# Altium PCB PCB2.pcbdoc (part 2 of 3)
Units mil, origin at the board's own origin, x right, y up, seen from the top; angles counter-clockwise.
Board outline 1771.65 x 2755.61 mil, 4 copper layers (Top Layer, Inner1, Inner2, Bottom Layer), stack 62.447 mil thick; 80 components, 88 nets, 409 pads, 183 vias.
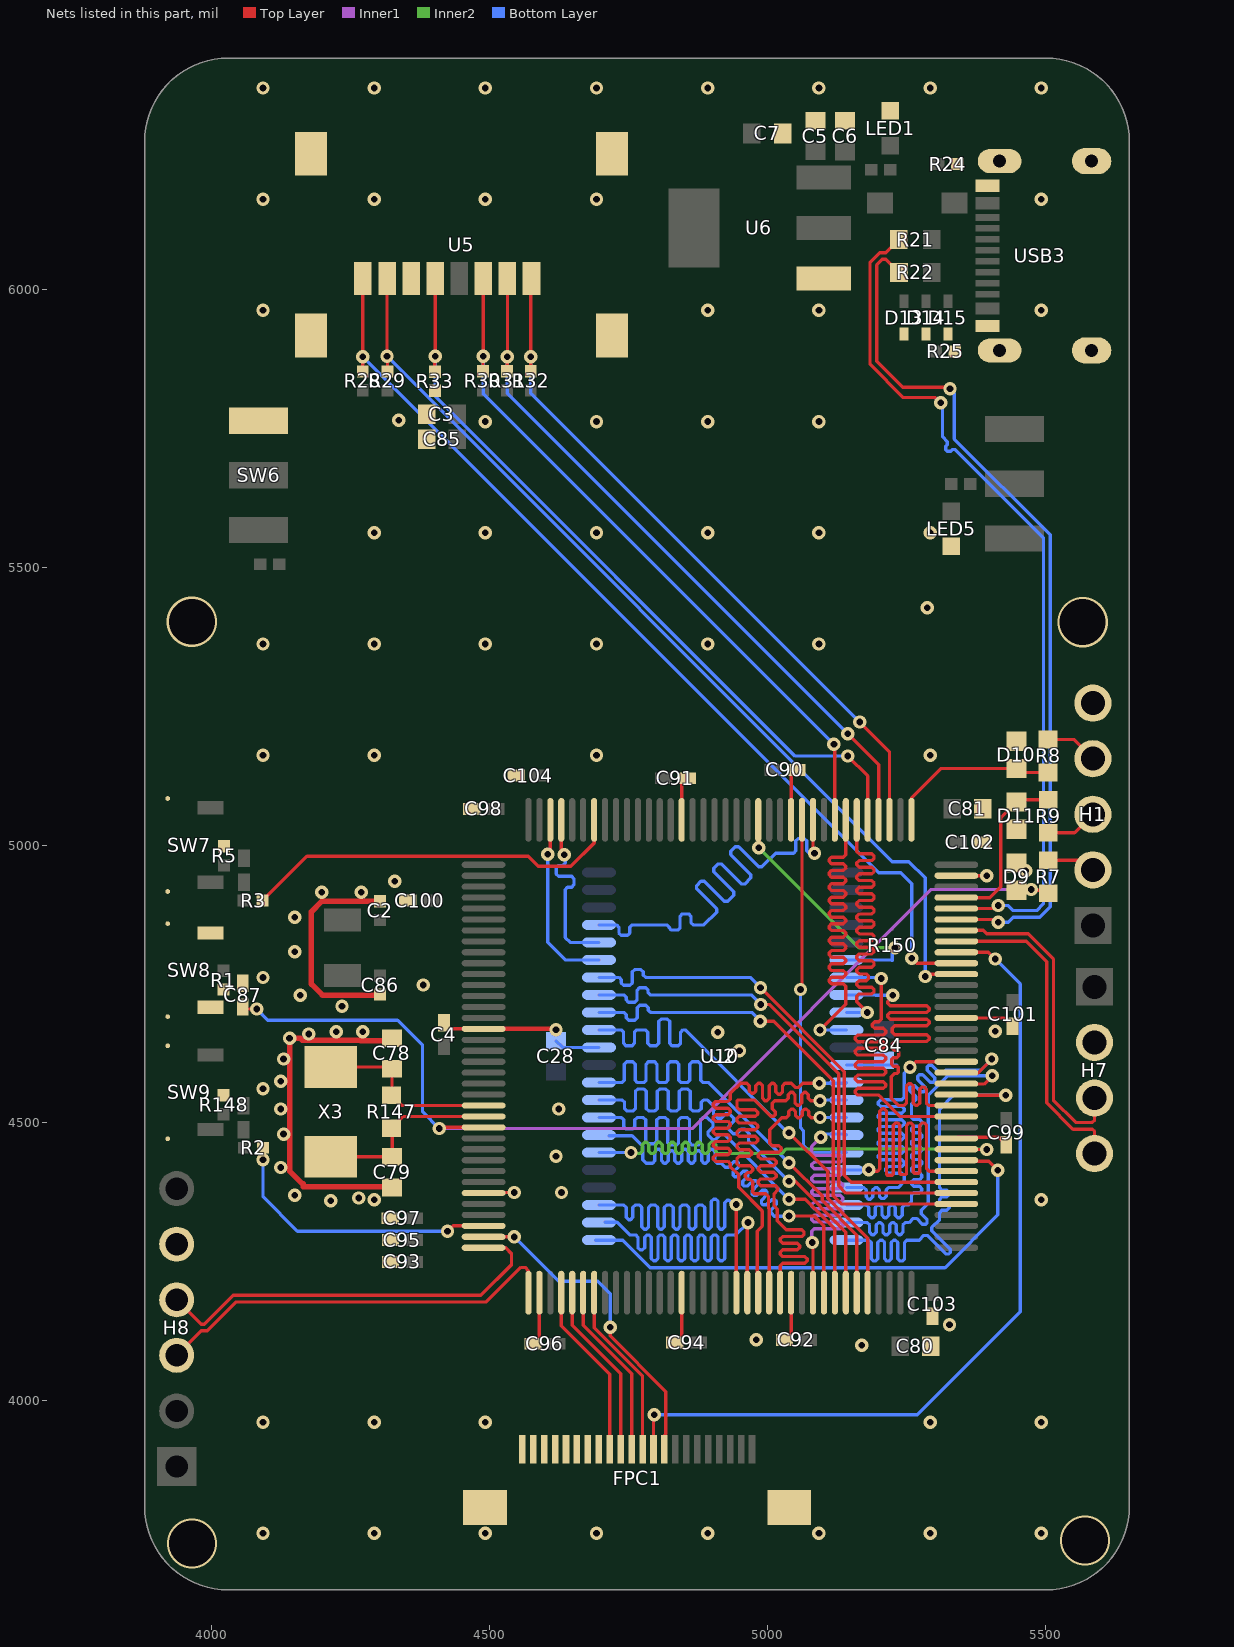
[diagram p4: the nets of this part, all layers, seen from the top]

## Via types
v1: diameter 24.02, hole 12.01, Top Layer to Bottom Layer, 179 vias
v2: diameter 90.55, hole 82.68, Top Layer to Bottom Layer, 4 vias

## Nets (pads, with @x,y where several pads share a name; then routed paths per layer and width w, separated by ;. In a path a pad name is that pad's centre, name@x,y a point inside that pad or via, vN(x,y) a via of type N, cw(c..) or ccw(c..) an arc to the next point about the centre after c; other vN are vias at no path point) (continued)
A10: U2.25 U10.56 | length 947.2
  Top Layer w6: U10.56@4944.53,4194.8 v1(4944.53,4353.18)
  Bottom Layer w6: U2.25@4697.34,4352.28 4742.07,4352.28 4746.31,4348.04 4746.31,4330.07 4750.55,4325.82 4754.07,4325.82 4758.31,4330.07 4758.31,4348.04 4762.55,4352.28 4770.31,4352.28 4774.55,4348.04 4774.55,4312.85 4778.8,4308.6 4782.31,4308.6 4786.55,4312.85 4786.55,4348.04 4790.8,4352.28 4798.55,4352.28 4802.8,4348.04 4802.8,4312.85 4807.04,4308.6 4810.55,4308.6 4814.8,4312.85 4814.8,4348.04 4819.04,4352.28 4826.8,4352.28 4831.04,4348.04 4831.04,4312.85 4835.28,4308.6 4838.8,4308.6 4843.04,4312.85 4843.04,4348.04 4847.28,4352.28 4855.04,4352.28 4859.28,4348.04 4859.28,4312.85 4863.53,4308.6 4867.04,4308.6 4871.28,4312.85 4871.28,4348.04 4875.53,4352.28 4883.28,4352.28 4887.53,4348.04 4887.53,4312.85 4891.77,4308.6 4895.28,4308.6 4899.53,4312.85 4899.53,4358.81 4903.77,4363.05 4907.28,4363.05 4911.53,4358.81 4911.53,4312.85 4915.77,4308.6 4919.28,4308.6 4923.53,4312.85 4923.53,4356.64 4927.77,4360.88 4931.28,4360.88 4935.53,4356.64 4935.53,4356.52 4939.77,4352.28 4943.63,4352.28 v1(4944.53,4353.18)
A11: U2.24 U10.57 | length 947.5
  Top Layer w6: U10.57@4964.21,4194.8 4964.21,4319.48 v1(4965.52,4320.79)
  Bottom Layer w6: U2.24@4708.95,4321.6 4729.9,4321.6 4752.91,4298.59 4763.29,4298.59 4767.53,4294.34 4767.53,4275.77 4771.78,4271.53 4775.29,4271.53 4779.53,4275.77 4779.53,4294.34 4783.78,4298.59 4787.29,4298.59 4791.53,4294.34 4791.53,4256.08 4795.78,4251.84 4799.29,4251.84 4803.53,4256.08 4803.53,4294.34 4807.78,4298.59 4811.29,4298.59 4815.53,4294.34 4815.53,4256.08 4819.78,4251.84 4823.29,4251.84 4827.53,4256.08 4827.53,4294.34 4831.78,4298.59 4835.29,4298.59 4839.53,4294.34 4839.53,4256.08 4843.78,4251.84 4847.29,4251.84 4851.53,4256.08 4851.53,4294.34 4855.78,4298.59 4859.29,4298.59 4863.53,4294.34 4863.53,4256.08 4867.78,4251.84 4871.29,4251.84 4875.53,4256.08 4875.53,4294.34 4879.78,4298.59 4883.29,4298.59 4887.53,4294.34 4887.53,4256.08 4891.78,4251.84 4895.29,4251.84 4899.53,4256.08 4899.53,4294.34 4903.78,4298.59 4907.29,4298.59 4911.53,4294.34 4911.53,4256.08 4915.78,4251.84 4919.29,4251.84 4923.53,4256.08 4923.53,4294.34 4927.78,4298.59 4943.59,4298.59 4965.52,4320.52 v1(4965.52,4320.79)
A12: U2.22 U10.87 | length 946.8
  Top Layer w6: U10.87@5340.2,4551.1 5341.3,4550 v1(5429.01,4550)
  Bottom Layer w6: U2.22@5142.66,4289.29 5182.78,4289.29 5187.02,4285.05 5187.02,4255.8 5191.26,4251.55 5194.78,4251.55 5199.02,4255.8 5199.02,4285.05 5203.26,4289.29 5206.78,4289.29 5211.02,4285.05 5211.02,4255.8 5215.26,4251.55 5218.78,4251.55 5223.02,4255.8 5223.02,4285.05 5227.26,4289.29 5230.78,4289.29 5235.02,4285.05 5235.02,4255.8 5239.26,4251.55 5242.78,4251.55 5247.02,4255.8 5247.02,4285.05 5251.26,4289.29 5273.31,4289.29 5281.61,4297.59 5287.61,4297.59 5320.83,4264.37 5326.83,4264.37 5329.31,4266.86 5329.31,4272.86 5296.1,4306.07 5296.1,4312.07 5310,4325.98 5310,4338.73 5314.24,4342.97 5322.98,4342.97 5327.23,4347.21 5327.23,4350.73 5322.98,4354.97 5314.24,4354.97 5310,4359.21 5310,4362.73 5314.24,4366.97 5322.98,4366.97 5327.23,4371.21 5327.23,4374.73 5322.98,4378.97 5314.24,4378.97 5310,4383.21 5310,4525 5335,4550 v1(5429.01,4550)
A13: U2.21 U10.88 | length 696.3
  Top Layer w6: U10.88@5340.2,4570.79 5340.99,4570 5390,4570 v1(5405,4585)
  Bottom Layer w6: U2.21@5142.66,4320.79 5179.91,4320.79 5184.15,4316.55 5184.15,4302.96 5188.4,4298.72 5191.91,4298.72 5196.15,4302.96 5196.15,4316.55 5200.4,4320.79 5203.91,4320.79 5208.15,4316.55 5208.15,4302.96 5212.4,4298.72 5215.91,4298.72 5220.15,4302.96 5220.15,4316.55 5224.4,4320.79 5227.91,4320.79 5232.15,4316.55 5232.15,4302.96 5236.4,4298.72 5239.91,4298.72 5244.15,4302.96 5244.15,4316.55 5248.4,4320.79 5255.15,4320.79 5262.61,4328.25 5268.61,4328.25 5279.12,4317.74 5285.12,4317.74 5287.6,4320.23 5287.6,4326.23 5277.09,4336.74 5277.09,4342.74 5290,4355.64 5290,4550 5325,4585 v1(5405,4585)
A14: U2.20 U10.89 | length 945.9
  Top Layer w6: U10.89@5340.2,4590.47 5379.5,4590.47 v1(5404.03,4615)
  Bottom Layer w6: U2.20@5142.66,4352.28 5178.39,4352.28 5182.64,4348.04 5182.64,4333.81 5186.88,4329.56 5190.39,4329.56 5194.64,4333.81 5194.64,4348.04 5198.88,4352.28 5202.39,4352.28 5206.64,4348.04 5206.64,4333.81 5210.88,4329.56 5214.39,4329.56 5218.64,4333.81 5218.64,4348.04 5222.88,4352.28 5226.39,4352.28 5230.64,4348.04 5230.64,4333.81 5234.88,4329.56 5238.39,4329.56 5242.64,4333.81 5242.64,4348.04 5246.88,4352.28 5253.55,4352.28 5259.55,4358.28 5259.55,4369.98 5263.79,4374.22 5273.98,4374.22 5278.23,4378.47 5278.23,4381.98 5273.98,4386.22 5263.79,4386.22 5259.55,4390.47 5259.55,4393.98 5263.79,4398.22 5273.98,4398.22 5278.23,4402.47 5278.23,4405.98 5273.98,4410.22 5263.79,4410.22 5259.55,4414.47 5259.55,4417.98 5263.79,4422.22 5273.98,4422.22 5278.23,4426.47 5278.23,4429.98 5273.98,4434.22 5263.79,4434.22 5259.55,4438.47 5259.55,4441.98 5263.79,4446.22 5273.98,4446.22 5278.23,4450.47 5278.23,4453.98 5273.98,4458.22 5263.79,4458.22 5259.55,4462.47 5259.55,4465.98 5263.79,4470.22 5273.98,4470.22 5278.23,4474.47 5278.23,4477.98 5273.98,4482.22 5263.79,4482.22 5259.55,4486.47 5259.55,4489.98 5263.79,4494.22 5273.98,4494.22 5278.23,4498.47 5278.23,4501.98 5273.98,4506.22 5263.79,4506.22 5259.55,4510.47 5259.55,4533.71 5267.46,4541.62 5267.46,4547.62 5256.72,4558.37 5256.72,4564.37 5259.2,4566.85 5265.2,4566.85 5275.94,4556.11 5281.94,4556.11 5284.43,4558.59 5284.43,4564.59 5270.91,4578.11 5270.91,4584.11 5273.4,4586.59 5279.4,4586.59 5292.91,4573.08 5298.91,4573.08 5301.4,4575.56 5301.4,4581.56 5287.88,4595.08 5287.88,4601.08 5290.37,4603.57 5296.37,4603.57 5309.89,4590.05 5315.89,4590.05 5320.85,4595.02 5384.05,4595.02 v1(5404.03,4615)
A15: U2.19 U10.90 | length 941
  Top Layer w6: v1(5256.95,4600) 5267.11,4610.16 U10.90@5340.2,4610.16
  Bottom Layer w6: U2.19@5142.66,4383.78 5173.7,4383.78 5177.94,4379.54 5177.94,4366.89 5182.18,4362.65 5185.7,4362.65 5189.94,4366.89 5189.94,4379.54 5194.18,4383.78 5197.7,4383.78 5201.94,4379.54 5201.94,4368.3 5206.18,4364.05 5209.7,4364.05 5213.94,4368.3 5213.94,4379.54 5218.18,4383.78 5235.77,4383.78 5246.7,4394.71 5246.7,4405.42 5242.46,4409.66 5217.63,4409.66 5213.39,4413.9 5213.39,4417.42 5217.63,4421.66 5242.46,4421.66 5246.7,4425.9 5246.7,4429.42 5242.46,4433.66 5204.28,4433.66 5200.04,4437.9 5200.04,4441.42 5204.28,4445.66 5242.46,4445.66 5246.7,4449.9 5246.7,4453.42 5242.46,4457.66 5204.28,4457.66 5200.04,4461.9 5200.04,4465.42 5204.28,4469.66 5242.46,4469.66 5246.7,4473.9 5246.7,4477.42 5242.46,4481.66 5204.28,4481.66 5200.04,4485.9 5200.04,4489.42 5204.28,4493.66 5242.46,4493.66 5246.7,4497.9 5246.7,4501.42 5242.46,4505.66 5204.28,4505.66 5200.04,4509.9 5200.04,4513.42 5204.28,4517.66 5242.46,4517.66 5246.7,4521.9 5246.7,4525.42 5242.46,4529.66 5204.28,4529.66 5200.04,4533.9 5200.04,4537.42 5204.28,4541.66 5242.46,4541.66 5246.7,4545.9 5246.7,4589.75 v1(5256.95,4600)
A16: U2.18 U10.80 | length 946.9
  Top Layer w6: v1(5182.53,4415.91) 5185.13,4413.31 5198.44,4413.31 5202.68,4417.55 5202.68,4521.15 5206.93,4525.4 5210.44,4525.4 5214.68,4521.15 5214.68,4407.32 5216.07,4405.93 5225.29,4405.93 5226.68,4407.32 5226.68,4495.71 5230.93,4499.96 5234.44,4499.96 5238.68,4495.71 5238.68,4408.77 5240.07,4407.39 5249.22,4407.39 5250.68,4408.84 5250.68,4495.71 5254.93,4499.96 5258.44,4499.96 5262.68,4495.71 5262.68,4411.33 5264.48,4409.54 5273.01,4409.54 5274.68,4411.21 5274.68,4495.71 5278.93,4499.96 5282.44,4499.96 5286.68,4495.71 5286.68,4417.55 5290.93,4413.31 U10.80@5340.2,4413.31
  Bottom Layer w6: U2.18@5142.66,4415.28 5181.9,4415.28 v1(5182.53,4415.91)
A17: U2.23 U10.81 | length 945
  Top Layer w6: U10.81@5340.2,4432.99 5341.89,4431.3 5398.7,4431.3 v1(5415,4415)
  Bottom Layer w6: U2.23@4691.26,4289.16 4739.99,4289.16 4789.36,4239.78 5319.87,4239.78 5414.94,4334.86 v1@5414.94,4414.04
A18: U2.28 U10.82 | length 946
  Top Layer w6: U10.82@5338.79,4452.37 5338.87,4452.3 v1(5395.08,4452.3)
  Inner2 w6: v1@4749.03,4445.05 4770.9,4445.05 4775.14,4449.29 4775.14,4460.98 4779.39,4465.22 4782.9,4465.22 4787.14,4460.98 4787.14,4449.29 4791.39,4445.05 4794.9,4445.05 4799.14,4449.29 4799.14,4460.98 4803.39,4465.22 4806.9,4465.22 4811.14,4460.98 4811.14,4449.29 4815.39,4445.05 4818.9,4445.05 4823.14,4449.29 4823.14,4460.98 4827.39,4465.22 4830.9,4465.22 4835.14,4460.98 4835.14,4449.29 4839.39,4445.05 4842.9,4445.05 4847.14,4449.29 4847.14,4460.98 4851.39,4465.22 4854.9,4465.22 4859.14,4460.98 4859.14,4449.29 4863.39,4445.05 4866.9,4445.05 4871.14,4449.29 4871.14,4460.98 4875.39,4465.22 4878.9,4465.22 4883.14,4460.98 4883.14,4449.29 4887.39,4445.05 4890.9,4445.05 4895.14,4449.29 4895.14,4460.98 4899.39,4465.22 4902.9,4465.22 4907.14,4460.98 4907.14,4449.29 4911.39,4445.05 5025.79,4445.05 5033.75,4453.01 5394.37,4453.01 v1(5395.08,4452.3)
  Bottom Layer w6: U2.28@4697.34,4446.77 v1(4755,4446.77)
BOOT0: R3.1 U10.138 | length 696.3
  Top Layer w6: R3.1@4092.04,4900 4172.04,4980 4570,4980 4588.32,4961.68 4646.68,4961.68 4688.62,5003.62 U10.138@4688.62,5045.2
CLK: H1.4 R8.1 | length 94.7
  Top Layer w6: R8.1@5505.48,5189.88 5551.24,5189.88 H1.4@5585.85,5155.26
CS: R150.2 U2.6 U10.123 | length 477.5
  Top Layer w5.98: U10.123@4983.9,5045.2 4985,5044.1 v1(4985,4995)
  Inner2 w5.98: v1(4985,4995) 5165,4815 v1(5230,4815)
  Bottom Layer w5.98: R150.2@5225,4792.44 5225,4810 v1(5230,4815)
  Bottom Layer w6: U2.6@5142.66,4793.23 5224.21,4793.23 R150.2@5225,4792.44
DAISY: FPC1.9 U10.35 | length 592
  Top Layer w6: U10.35@4489.8,4295.2 4490,4295 v1(4545,4295) ; v1(4717.39,4132.3) 4717.39,4116.78 4817.78,4016.38 4817.78,3940.42 4815.09,3937.72 FPC1.9@4815.09,3913.35
  Bottom Layer w6: v1(4545,4295) 4625,4215 4695,4215 4717.39,4192.61 v1(4717.39,4132.3)
DIO: H1.3 R9.1 | length 93.9
  Top Layer w6: R9.1@5505.63,5022.3 5552.9,5022.3 H1.3@5585.85,5055.26
GND: C2.1 C3.1 C4.1 C5.1 C6.1 C7.2 C28.2 C78.1 C79.1 C80.2 C81.2 C84.2 C85.1 C86.1 C87.1 C90.2 C91.2 C92.2 C93.2 C94.2 C95.2 C96.2 C97.2 C98.2 C99.2 C100.2 C101.2 C102.2 C103.2 C104.1 D9.2 D10.2 D11.2 D13.1 D14.1 D15.1 FPC1.15 FPC1.16 FPC1.17 FPC1.18 FPC1.19 FPC1.20 FPC1.21 FPC1.22 FPC1.23 FPC1.24 H1.5 H7.2 H8.5 LED1.1 LED5.1 R5.2 R24.2 R25.2 R33.2 R148.2 SW6.3 SW7.3 SW7.4 SW8.2 SW8.3 SW8.4 SW9.3 SW9.4 U2.12 U2.34 U5.6 U5.9 U5.10 U5.11 U5.12 U6.1 U10.16 U10.31 U10.38 U10.51 U10.61 U10.83 U10.94 U10.107 U10.120 U10.130 USB3.1 USB3.12 USB3.13 USB3.14 | length 2169.7
  Top Layer w6: C4.1@4418.54,4680.5 4429.83,4669.21 U10.16@4489.8,4669.21 ; U10.31@4489.8,4373.94 4490.86,4375 v1(4545,4375) ; C96.2@4578.7,4102.72 4590.2,4114.22 U10.38@4590.2,4194.8 ; C94.2@4833.54,4105 4846.1,4117.56 U10.51@4846.1,4194.8 ; U10.130@4846.1,5045.2 4846.1,5109.64 C91.2@4856.46,5120 ; C92.2@5031.05,4109.69 5042.95,4121.59 U10.61@5042.95,4194.8 ; U10.120@5042.95,5045.2 5042.95,5124.76 C90.2@5053.19,5135 ; U10.83@5340.2,4472.36 5342.2,4474.36 5416.56,4474.36 C99.2@5429.86,4461.05 ; U10.94@5340.2,4688.9 5426.3,4688.9 C101.2@5441.34,4673.86 ; U10.107@5340.2,4944.8 v1(5395.2,4944.8)
  Top Layer w7.87: U10.16@4489.8,4669.21 4618.7,4669.21 v1(4620,4667.91)
  Top Layer w10: C2.1@4303.59,4899.16 4199.16,4899.16 4180,4880 4180,4750 4200,4730 4302.58,4730 C86.1@4303.65,4731.06 ; C78.1@4325,4652.56 4320,4647.56 4268.33,4647.56 4266.79,4649.1 4163.21,4649.1 4159.74,4652.56 v1(4140.79,4652.56) 4140.79,4413.32 4163.21,4390.9 4164.36,4390.9 4165,4390.27 4165,4385 4324.1,4385 C79.1@4325.2,4383.89
  Bottom Layer w6: C28.2@4620,4647.56 4631.81,4635.75 U2.34@4697.34,4635.75 ; U2.12@5142.66,4604.25 5233.19,4604.25
  other v1: 4093.03,3761.73 4293.03,3761.73 4493.03,3761.73 4693.03,3761.73 4893.03,3761.73 5093.03,3761.73 5293.03,3761.73 5493.03,3761.73 4093.03,3961.73 4293.03,3961.73 4493.03,3961.73 5293.03,3961.73 5493.03,3961.73 5170,4100 4980,4110 5328.03,4136.73 4215,4360 4293.03,4361.73 5493.03,4361.73 4265,4365 4150,4370 4630,4375 4125,4420 4620,4440 4130,4480 4125,4525 4625,4525 4093.03,4561.73 4125,4575 4130,4615 4950,4630 4175,4660 4911.06,4663.17 4225,4664.01 4272.56,4664.01 5410,4665 4235,4710 4160,4730 4381.02,4748.1 4093.03,4761.73 4150,4808.18 4150,4870 4198.73,4915 4270,4915 4330,4935 5465,4953.79 4093.03,5161.73 4293.03,5161.73 4693.03,5161.73 5293.03,5161.73 4093.03,5361.73 4293.03,5361.73 4493.03,5361.73 4693.03,5361.73 4893.03,5361.73 5093.03,5361.73 5288.03,5426.73 4293.03,5561.73 4493.03,5561.73 4693.03,5561.73 4893.03,5561.73 5093.03,5561.73 5293.03,5561.73 4493.03,5761.73 4693.03,5761.73 4893.03,5761.73 5093.03,5761.73 4336.89,5764.22 4093.03,5961.73 4893.03,5961.73 5093.03,5961.73 5493.03,5961.73 4093.03,6161.73 4293.03,6161.73 4493.03,6161.73 4693.03,6161.73 5493.03,6161.73 4093.03,6361.73 4293.03,6361.73 4493.03,6361.73 4693.03,6361.73 4893.03,6361.73 5093.03,6361.73 5293.03,6361.73 5493.03,6361.73
  other v2: 3965.18,3743.42 5571.73,3748.98 5567.35,5401.03 3964.91,5401.64
IO0: U2.7 U10.85 | length 947.3
  Top Layer w6: v1(5205,4760) 5205,4686.39 5200.76,4682.15 5193.1,4682.15 5188.86,4677.91 5188.86,4674.39 5193.1,4670.15 5208.98,4670.15 5213.23,4665.91 5213.23,4662.39 5208.98,4658.15 5162.71,4658.15 5158.47,4653.91 5158.47,4650.39 5162.71,4646.15 5208.98,4646.15 5213.23,4641.91 5213.23,4638.39 5208.98,4634.15 5162.71,4634.15 5158.47,4629.91 5158.47,4626.39 5162.71,4622.15 5208.98,4622.15 5213.23,4617.91 5213.23,4614.39 5208.98,4610.15 5162.71,4610.15 5158.47,4605.91 5158.47,4602.39 5162.71,4598.15 5208.98,4598.15 5213.23,4593.91 5213.23,4590.39 5208.98,4586.15 5162.71,4586.15 5158.47,4581.91 5158.47,4578.39 5162.71,4574.15 5208.98,4574.15 5213.23,4569.91 5213.23,4566.39 5208.98,4562.15 5162.71,4562.15 5158.47,4557.91 5158.47,4554.39 5162.71,4550.15 5200.76,4550.15 5205,4545.91 5205,4545 5238.27,4511.73 U10.85@5340.2,4511.73
  Bottom Layer w6: U2.7@5142.66,4761.73 5203.27,4761.73 v1(5205,4760)
IO1: U2.8 U10.86 | length 946.8
  Top Layer w6: v1(5225.99,4730) 5225,4729.01 5225,4726.81 5216.77,4718.58 5216.77,4715.06 5221.02,4710.82 5286.98,4710.82 5291.23,4706.58 5291.23,4703.06 5286.98,4698.82 5221.02,4698.82 5216.77,4694.58 5216.77,4691.06 5221.02,4686.82 5286.98,4686.82 5291.23,4682.58 5291.23,4679.06 5286.98,4674.82 5229.24,4674.82 5225,4670.58 5225,4662.82 5229.24,4658.58 5286.98,4658.58 5291.23,4654.34 5291.23,4650.82 5286.98,4646.58 5229.24,4646.58 5225,4642.34 5225,4634.58 5229.24,4630.34 5233.49,4630.34 5236.57,4627.25 5236.57,4620.55 5233.33,4617.31 5226.44,4617.31 5223.77,4614.64 5223.77,4605.38 5227.06,4602.09 5233.93,4602.09 5235.96,4600.06 5235.96,4591.26 5233.7,4589 5229.24,4589 5223.24,4583 5223.24,4544.23 5236.05,4531.42 5246.2,4531.42 5250.44,4535.66 5250.44,4566.58 5254.69,4570.82 5258.2,4570.82 5262.44,4566.58 5262.44,4535.66 5266.69,4531.42 5270.2,4531.42 5274.44,4535.66 5274.44,4560.58 5278.69,4564.82 5282.2,4564.82 5286.44,4560.58 5286.44,4535.66 5290.69,4531.42 U10.86@5340.2,4531.42
  Bottom Layer w6: U2.8@5142.66,4730.24 5194.76,4730.24 5195,4730 v1(5225.99,4730)
IO2: U2.9 U10.114 | length 947
  Top Layer w6: U10.114@5161.06,5045.2 5161.06,4988.28 5165.3,4984.04 5187.93,4984.04 5192.18,4979.8 5192.18,4976.28 5187.93,4972.04 5165.3,4972.04 5161.06,4967.8 5161.06,4964.28 5165.3,4960.04 5187.93,4960.04 5192.18,4955.8 5192.18,4952.28 5187.93,4948.04 5165.3,4948.04 5161.06,4943.8 5161.06,4940.28 5165.3,4936.04 5187.93,4936.04 5192.18,4931.8 5192.18,4928.28 5187.93,4924.04 5165.3,4924.04 5161.06,4919.8 5161.06,4916.28 5165.3,4912.04 5187.93,4912.04 5192.18,4907.8 5192.18,4904.28 5187.93,4900.04 5165.3,4900.04 5161.06,4895.8 5161.06,4892.28 5165.3,4888.04 5187.93,4888.04 5192.18,4883.8 5192.18,4880.28 5187.93,4876.04 5165.3,4876.04 5161.06,4871.8 5161.06,4868.28 5165.3,4864.04 5187.93,4864.04 5192.18,4859.8 5192.18,4856.28 5187.93,4852.04 5165.3,4852.04 5161.06,4847.8 5161.06,4844.28 5165.3,4840.04 5187.93,4840.04 5192.18,4835.8 5192.18,4832.28 5187.93,4828.04 5165.3,4828.04 5161.06,4823.8 5161.06,4820.28 5165.3,4816.04 5187.93,4816.04 5192.18,4811.8 5192.18,4808.28 5187.93,4804.04 5165.3,4804.04 5161.06,4799.8 5161.06,4796.28 5165.3,4792.04 5187.93,4792.04 5192.18,4787.8 5192.18,4784.28 5187.93,4780.04 5165.3,4780.04 5161.06,4775.8 5161.06,4772.28 5165.3,4768.04 5178.01,4768.04 5182.25,4763.8 5182.25,4760.28 5178.01,4756.04 5165.3,4756.04 5161.06,4751.8 5161.06,4748.28 5165.3,4744.04 5187.93,4744.04 5192.18,4739.8 5192.18,4736.28 5187.93,4732.04 5165.3,4732.04 5161.06,4727.8 5161.06,4717.68 v1(5180,4698.74)
  Bottom Layer w6: U2.9@5142.66,4698.74 v1(5180,4698.74)
IO3: U2.10 U10.115 | length 946.3
  Top Layer w6: v1(5095,4667.24) 5141.38,4713.62 5141.38,4745.99 5137.14,4750.23 5115.58,4750.23 5111.33,4754.47 5111.33,4757.99 5115.58,4762.23 5137.14,4762.23 5141.38,4766.47 5141.38,4769.99 5137.14,4774.23 5115.58,4774.23 5111.33,4778.47 5111.33,4781.99 5115.58,4786.23 5137.14,4786.23 5141.38,4790.47 5141.38,4793.99 5137.14,4798.23 5115.58,4798.23 5111.33,4802.47 5111.33,4805.99 5115.58,4810.23 5137.14,4810.23 5141.38,4814.47 5141.38,4817.99 5137.14,4822.23 5115.58,4822.23 5111.33,4826.47 5111.33,4829.99 5115.58,4834.23 5137.14,4834.23 5141.38,4838.47 5141.38,4841.99 5137.14,4846.23 5115.58,4846.23 5111.33,4850.47 5111.33,4853.99 5115.58,4858.23 5137.14,4858.23 5141.38,4862.47 5141.38,4865.99 5137.14,4870.23 5115.58,4870.23 5111.33,4874.47 5111.33,4877.99 5115.58,4882.23 5137.14,4882.23 5141.38,4886.47 5141.38,4889.99 5137.14,4894.23 5115.58,4894.23 5111.33,4898.47 5111.33,4901.99 5115.58,4906.23 5137.14,4906.23 5141.38,4910.47 5141.38,4913.99 5137.14,4918.23 5115.58,4918.23 5111.33,4922.47 5111.33,4925.99 5115.58,4930.23 5137.14,4930.23 5141.38,4934.47 5141.38,4937.99 5137.14,4942.23 5115.58,4942.23 5111.33,4946.47 5111.33,4949.99 5115.58,4954.23 5137.14,4954.23 5141.38,4958.47 5141.38,4961.99 5137.14,4966.23 5115.58,4966.23 5111.33,4970.47 5111.33,4973.99 5115.58,4978.23 5137.14,4978.23 5141.38,4982.47 U10.115@5141.38,5045.2
  Bottom Layer w6: v1(5095,4667.24) U2.10@5142.66,4667.24
IO4: U2.13 U10.58 | length 946.6
  Top Layer w6: U10.58@4982.32,4223.11 4982.32,4305.57 4991.25,4314.5 4991.26,4341.62 4948.51,4384.37 4948.51,4406.49 4933.79,4421.21 4933.79,4426.45 4929.55,4430.69 4907.44,4430.69 4903.2,4434.93 4903.2,4438.45 4907.44,4442.69 4929.55,4442.69 4933.79,4446.93 4933.79,4450.45 4929.55,4454.69 4907.44,4454.69 4903.2,4458.93 4903.2,4462.45 4907.44,4466.69 4929.55,4466.69 4933.79,4470.93 4933.79,4474.45 4929.55,4478.69 4907.44,4478.69 4903.2,4482.93 4903.2,4486.45 4907.44,4490.69 4929.55,4490.69 4933.79,4494.93 4933.79,4498.45 4929.55,4502.69 4907.44,4502.69 4903.2,4506.93 4903.2,4510.45 4907.44,4514.69 4929.55,4514.69 4933.79,4518.93 4933.79,4522.45 4929.55,4526.69 4907.44,4526.69 4903.2,4530.93 4903.2,4534.45 4907.44,4538.69 4929.55,4538.69 4933.79,4542.93 4933.79,4553.26 4952.06,4571.54 4963.39,4571.54 4967.63,4567.29 4967.63,4557.42 4971.88,4553.18 4975.39,4553.18 4979.63,4557.42 4979.63,4567.29 4983.88,4571.54 4987.39,4571.54 4991.63,4567.29 4991.63,4544.32 4995.88,4540.08 4999.39,4540.08 5003.63,4544.32 5003.63,4567.29 5007.88,4571.54 5011.39,4571.54 5015.63,4567.29 5015.63,4556.02 5019.88,4551.77 5023.39,4551.77 5027.63,4556.02 5027.63,4567.29 5031.88,4571.54 5043.64,4571.54 5051.52,4563.66 5055.64,4563.66 5063.52,4571.54 v1(5093.78,4571.54)
  Bottom Layer w6: v1(5093.78,4571.54) 5141.44,4571.54 U2.13@5142.66,4572.76
IO5: U2.14 U10.59 | length 946.4
  Top Layer w6: U10.59@5003.58,4194.8 5003.58,4345.72 5002.25,4347.04 5002.25,4367.75 4997.18,4372.82 4976.47,4372.82 4973.93,4375.37 4973.93,4394.57 4969.68,4398.81 4964.53,4398.81 4960.29,4403.05 4960.29,4406.57 4964.53,4410.81 4969.68,4410.81 4973.93,4415.05 4973.93,4418.57 4969.68,4422.81 4949.35,4422.81 4945.11,4427.05 4945.26,4427.05 4945.56,4427.35 4945.56,4435.57 4949.8,4439.82 4967.93,4439.82 4972.17,4444.06 4972.17,4447.57 4967.93,4451.82 4949.8,4451.82 4945.56,4456.06 4945.56,4459.57 4949.8,4463.82 4978.74,4463.82 4982.98,4468.06 4982.98,4471.57 4978.74,4475.82 4949.8,4475.82 4945.56,4480.06 4945.56,4483.57 4949.8,4487.82 4978.74,4487.82 4982.98,4492.06 4982.98,4495.57 4978.74,4499.82 4949.8,4499.82 4945.56,4504.06 4945.56,4507.57 4949.8,4511.82 4978.74,4511.82 4982.98,4516.06 4982.98,4519.57 4978.74,4523.82 4949.8,4523.82 4945.56,4528.06 4945.56,4539.4 4947.56,4541.41 4976.6,4541.41 5006.04,4511.97 5012.04,4511.97 5014.52,4514.45 5014.52,4520.45 5009.31,4525.66 5009.31,4535.84 5013.48,4540 5033.72,4540 5037.96,4544.24 5037.96,4550.76 5042.2,4555 5045.72,4555 5049.96,4550.76 5049.96,4536.37 5054.2,4532.13 5057.72,4532.13 5061.96,4536.37 5061.96,4550.76 5066.2,4555 5069.72,4555 5073.96,4550.76 5073.96,4544.24 5078.2,4540 v1(5095,4540)
  Bottom Layer w6: v1(5095,4540) 5096.26,4541.26 U2.14@5142.66,4541.26
IO6: U2.15 U10.60 | length 899.9
  Top Layer w6: U10.60@5023.27,4194.8 5023.31,4243.48 5027.55,4247.72 5067.76,4247.72 5072,4251.96 5072,4255.48 5067.76,4259.72 5027.55,4259.72 5023.31,4263.96 5023.31,4267.48 5027.55,4271.72 5054.03,4271.72 5058.27,4275.96 5058.27,4279.48 5054.03,4283.72 5027.55,4283.72 5023.31,4287.96 5023.31,4291.48 5027.55,4295.72 5062.05,4295.72 5066.29,4299.96 5066.29,4303.48 5062.05,4307.72 5034.53,4307.72 5018.27,4323.98 5018.27,4345.19 5012.27,4351.19 5012.27,4372.4 5019.32,4379.45 5019.32,4382.97 5015.08,4387.21 4988.18,4387.21 4983.94,4391.45 4983.94,4394.97 4988.18,4399.21 5012.08,4399.21 5016.32,4403.45 5016.32,4406.97 5012.08,4411.21 4988.18,4411.21 4983.94,4415.45 4983.94,4418.97 4988.18,4423.21 5012.08,4423.21 5016.32,4427.45 5016.32,4430.97 5012.08,4435.21 4988.18,4435.21 4983.94,4439.45 4983.94,4442.97 4988.18,4447.21 5020.8,4447.21 5025.04,4451.45 5025.04,4454.97 5020.8,4459.21 5008.74,4459.21 5004.49,4463.45 5004.49,4487.77 5025.9,4509.18 5034.58,4509.18 5038.82,4513.43 5038.82,4520.76 5043.07,4525 5046.58,4525 5050.82,4520.76 5050.82,4513.43 5055.07,4509.18 5058.58,4509.18 5062.82,4513.43 5062.82,4520.76 5067.07,4525 5070.58,4525 5074.82,4520.76 5074.82,4513.43 5079.07,4509.18 v1@5092.95,4509.18
  Bottom Layer w6: v1(5095,4509.76) U2.15@5142.66,4509.76
IO7: U2.16 U10.63 | length 946.1
  Top Layer w6: v1(5081.02,4285) 5082.32,4283.7 U10.63@5082.32,4194.8
  Inner1 w6: v1(5081.02,4285) 5080,4286.02 5080,4305.52 5084.24,4309.76 5131.53,4309.76 5135.77,4314 5135.77,4317.52 5131.53,4321.76 5084.24,4321.76 5080,4326 5080,4329.52 5084.24,4333.76 5131.53,4333.76 5135.77,4338 5135.77,4341.52 5131.53,4345.76 5084.24,4345.76 5080,4350 5080,4353.52 5084.24,4357.76 5131.53,4357.76 5135.77,4362 5135.77,4365.52 5131.53,4369.76 5084.24,4369.76 5080,4374 5080,4377.52 5084.24,4381.76 5131.53,4381.76 5135.77,4386 5135.77,4389.52 5131.53,4393.76 5084.24,4393.76 5080,4398 5080,4401.52 5084.24,4405.76 5131.53,4405.76 5135.77,4410 5135.77,4413.52 5131.53,4417.76 5084.24,4417.76 5080,4422 5080,4425.52 5084.24,4429.76 5131.53,4429.76 5135.77,4434 5135.77,4437.52 5131.53,4441.76 5084.24,4441.76 5080,4446 5080,4457.76 v1(5096.24,4474)
  Bottom Layer w6: v1(5096.24,4474) 5102.24,4480 5140.93,4480 U2.16@5142.66,4478.27
IO8: U2.29 U10.64 | length 946.3
  Top Layer w6: v1(5039.26,4332.67) 5084.18,4332.67 5102.01,4314.84 U10.64@5102.01,4194.8
  Bottom Layer w6: U2.29@4715.67,4477.22 4756.8,4477.22 ; 4756.9,4477.2 4775.99,4458.11 4775.99,4434.01 4782.2,4427.8 4793.72,4427.8 4797.97,4432.04 4797.97,4448.55 4802.21,4452.79 4805.72,4452.79 4809.97,4448.55 4809.97,4432.04 4814.21,4427.8 4817.72,4427.8 4821.97,4432.04 4821.97,4445.55 4826.21,4449.79 4829.72,4449.79 4833.97,4445.55 4833.97,4432.04 4838.21,4427.8 4841.72,4427.8 4845.97,4432.04 4845.97,4448.55 4850.21,4452.79 4853.72,4452.79 4857.97,4448.55 4857.97,4432.04 4862.21,4427.8 4865.72,4427.8 4869.97,4432.04 4869.97,4445.55 4874.21,4449.79 4877.72,4449.79 4881.97,4445.55 4881.97,4432.04 4886.21,4427.8 4889.72,4427.8 4893.97,4432.04 4893.97,4448.55 4898.21,4452.79 4901.72,4452.79 4905.97,4448.55 4905.97,4432.04 4910.21,4427.8 4917.16,4427.8 4924.48,4420.48 4930.48,4420.48 4940.02,4430.01 4946.02,4430.01 4948.5,4427.53 4948.5,4421.53 4938.97,4411.99 4938.97,4405.99 4941.45,4403.51 4947.45,4403.51 4956.99,4413.04 4962.99,4413.04 4965.48,4410.56 4965.48,4404.56 4955.94,4395.02 4955.94,4389.02 4958.42,4386.53 4964.42,4386.53 4973.96,4396.07 4979.96,4396.07 4982.45,4393.59 4982.45,4387.59 4972.91,4378.05 4972.91,4372.05 4975.39,4369.56 4981.39,4369.56 4990.93,4379.1 4996.93,4379.1 4999.42,4376.62 4999.42,4370.62 4989.88,4361.08 4989.88,4355.08 4992.36,4352.59 4998.36,4352.59 5007.9,4362.13 5013.9,4362.13 5016.39,4359.65 5016.39,4353.65 5006.85,4344.11 5006.85,4338.11 5012.89,4332.07 v1@5039.43,4332.07
IO9: U2.30 U10.65 | length 948.8
  Top Layer w6: v1(5039.07,4362.68) 5068.34,4362.68 5121.69,4309.33 U10.65@5121.69,4194.8
  Bottom Layer w6: U2.30@4697.34,4509.76 4737.88,4509.76 4742.12,4505.52 4742.12,4493.24 4746.37,4488.99 4757.57,4488.99 4761.81,4493.24 4761.81,4505.52 4766.05,4509.76 4777.25,4509.76 4781.49,4505.52 4781.49,4466.69 4785.74,4462.45 4796.94,4462.45 4801.18,4466.69 4801.18,4505.52 4805.42,4509.76 4816.62,4509.76 4820.86,4505.52 4820.86,4464.51 4825.11,4460.27 4836.31,4460.27 4840.55,4464.51 4840.55,4505.52 4844.79,4509.76 4855.99,4509.76 4860.23,4505.52 4860.23,4464.51 4864.48,4460.27 4875.68,4460.27 4879.92,4464.51 4879.92,4505.52 4884.16,4509.76 4891.98,4509.76 4902.52,4499.22 4902.52,4493.22 4893.51,4484.2 4893.51,4478.2 4901.43,4470.28 4907.43,4470.28 4916.44,4479.3 4922.44,4479.3 v1(5039.07,4362.68)
IO10: U2.31 U10.66 | length 944.5
  Top Layer w6: v1(5039.07,4394.92) 5050.26,4394.92 5141.38,4303.8 U10.66@5141.38,4194.8
  Bottom Layer w6: U2.31@4697.34,4541.26 4739.09,4541.26 4743.33,4537.02 4743.33,4525.78 4747.58,4521.53 4758.78,4521.53 4763.02,4525.78 4763.02,4556.74 4767.26,4560.99 4778.46,4560.99 4782.7,4556.74 4782.7,4525.78 4786.95,4521.53 4798.15,4521.53 4802.39,4525.78 4802.39,4556.74 4806.63,4560.99 4817.83,4560.99 4822.07,4556.74 4822.07,4525.78 4826.32,4521.53 4837.52,4521.53 4841.76,4525.78 4841.76,4556.74 4846,4560.99 4857.2,4560.99 4861.44,4556.74 4861.44,4525.78 4865.69,4521.53 4876.89,4521.53 4881.13,4525.78 4881.13,4537.02 4885.37,4541.26 4892.73,4541.26 4904.55,4529.44 4904.55,4523.44 4903.34,4522.24 4903.34,4516.24 4911.26,4508.32 4917.26,4508.32 4925.67,4516.73 4931.67,4516.73 4939.59,4508.81 4939.59,4502.81 4931.18,4494.4 4931.18,4488.4 4939.1,4480.48 4945.1,4480.48 4953.51,4488.89 4959.51,4488.89 4967.43,4480.97 4967.43,4474.97 4966.23,4473.76 4966.23,4467.76 v1(5039.07,4394.92)
IO11: U2.32 U10.67 | length 945.2
  Top Layer w6: v1(5039.07,4428.64) 5098.75,4368.96 5098.75,4360.59 5161.06,4298.29 U10.67@5161.06,4194.8
  Bottom Layer w6: U2.32@4697.34,4572.76 4738.4,4572.76 4742.64,4577 4742.64,4605.92 4746.88,4610.16 4758.08,4610.16 4762.33,4605.92 4762.33,4577 4766.57,4572.76 4777.77,4572.76 4782.01,4577 4782.01,4605.92 4786.25,4610.16 4797.45,4610.16 4801.7,4605.92 4801.7,4577 4805.94,4572.76 4817.14,4572.76 4821.38,4577 4821.38,4605.92 4825.62,4610.16 4836.82,4610.16 4841.07,4605.92 4841.07,4577 4845.31,4572.76 4856.51,4572.76 4860.75,4577 4860.75,4605.92 4864.99,4610.16 4876.19,4610.16 4880.44,4605.92 4880.44,4577 4884.68,4572.76 4894.95,4572.76 v1(5039.07,4428.64)
IO12: U2.35 U10.68 | length 944.7
  Top Layer w6: v1(5039.07,4482.68) 5108.77,4412.97 5108.77,4364.74 5180.75,4292.76 U10.68@5180.75,4194.8
  Bottom Layer w6: U2.35@4697.34,4667.24 4737.25,4667.24 4741.49,4663 4741.49,4643.09 4745.73,4638.85 4756.93,4638.85 4761.17,4643.09 4761.17,4663 4765.42,4667.24 4780.86,4667.24 4785.1,4663 4785.1,4643.09 4789.35,4638.85 4800.54,4638.85 4804.79,4643.09 4804.79,4682.72 4809.03,4686.97 4820.23,4686.97 4824.47,4682.72 4824.47,4643.09 4828.72,4638.85 4839.91,4638.85 4844.16,4643.09 4844.16,4663 4848.4,4667.24 4852.76,4667.24 5037.32,4482.68 v1(5039.07,4482.68)
IO13: U2.36 U10.77 | length 945.2
  Top Layer w6: v1(4987.56,4683.22) 5011.78,4683.22 5118.79,4576.21 5118.79,4368.89 5133.43,4354.25 U10.77@5340.2,4354.25
  Bottom Layer w6: U2.36@4697.34,4698.74 4742.2,4698.74 4746.44,4694.5 4746.44,4689.28 4750.69,4685.04 4761.89,4685.04 4766.13,4689.28 4766.13,4707.37 4770.37,4711.62 4781.57,4711.62 4785.81,4707.37 4785.81,4702.98 4790.06,4698.74 4972.05,4698.74 v1(4987.56,4683.22)
IO14: U2.37 U10.78 | length 946.2
  Top Layer w6: v1(4988.22,4713.22) 5003.75,4713.22 5128.8,4588.17 5128.8,4386.87 5141.73,4373.94 U10.78@5340.2,4373.94
  Bottom Layer w6: U2.37@4697.34,4730.24 4741.97,4730.24 4746.21,4726 4746.21,4721.31 4750.46,4717.06 4761.66,4717.06 4765.9,4721.31 4765.9,4739.17 4770.14,4743.42 4781.34,4743.42 4785.58,4739.17 4785.58,4734.48 4789.83,4730.24 4971.21,4730.24 v1(4988.22,4713.22)
IO15: U2.38 U10.79 | length 946.7
  Top Layer w6: v1(4987.98,4743.22) 5138.82,4592.39 5138.82,4405.93 5151.13,4393.62 U10.79@5340.2,4393.62
  Bottom Layer w6: U2.38@4697.34,4761.73 4733.41,4761.73 4737.65,4757.49 4737.65,4751.72 4741.89,4747.48 4753.09,4747.48 4757.33,4751.72 4757.33,4771.74 4761.58,4775.98 4772.78,4775.98 4777.02,4771.74 4777.02,4765.97 4781.26,4761.73 4969.48,4761.73 v1(4987.98,4743.22)
LB: U2.39 U10.142 | length 327.6
  Top Layer w6: v1(4605.14,4983.31) 4609.88,4988.05 U10.142@4609.88,5045.2
  Bottom Layer w6: v1(4605.14,4983.31) 4605.14,4824.86 4636.77,4793.23 U2.39@4697.34,4793.23
NRST: C87.2 D9.1 R1.2 R7.2 SW8.1 U10.25 | length 1897.2
  Top Layer w6: C87.2@4056.63,4708.49 4060.12,4705 v1(4081.63,4705) ; v1(4410,4490) 4412.05,4492.05 U10.25@4489.8,4492.05 ; D9.1@5448.5,4918.61 5500.37,4918.61 R7.2@5505.62,4913.35
  Inner1 w6: v1(4410,4490) 4865,4490 5295,4920 v1(5475,4920)
  Bottom Layer w6: v1(4081.63,4705) 4101.63,4685 4335,4685 4380,4640 4380,4520 v1(4410,4490)
OE: U2.41 U10.118 | length 943.8
  Top Layer w6: U10.118@5082.32,5045.2 5082.32,4987.68 v1(5085,4985)
  Bottom Layer w6: U2.41@4697.34,4856.22 4729.02,4856.22 4733.27,4851.98 4733.27,4841.68 4737.51,4837.44 4748.71,4837.44 4752.95,4841.68 4752.95,4851.98 4757.19,4856.22 4819.27,4856.22 4823.51,4851.98 4823.51,4851.24 4827.75,4847 4838.95,4847 4843.2,4851.24 4843.2,4871.7 4847.44,4875.95 4858.64,4875.95 4862.88,4871.7 4862.88,4860.46 4867.12,4856.22 4886.22,4856.22 4909.01,4879.01 4909.01,4885.01 4872.89,4921.13 4872.89,4927.13 4880.81,4935.05 4886.81,4935.05 4922.93,4898.93 4928.93,4898.93 4939.85,4909.85 4939.85,4915.85 4903.73,4951.97 4903.73,4957.97 4911.65,4965.89 4917.65,4965.89 4953.77,4929.77 4959.77,4929.77 4970.69,4940.69 4970.69,4946.69 4934.57,4982.81 4934.57,4988.81 4942.49,4996.73 4948.49,4996.73 4984.61,4960.61 4990.61,4960.61 5015,4985 5047.32,4985 5051.56,4989.24 5051.56,5007.39 5055.8,5011.64 5067,5011.64 5071.24,5007.39 5071.24,4989.24 5075.49,4985 v1(5085,4985)
OSC25_IN: C78.2 R147.2 U10.23 X3.2 | length 332.9
  Top Layer w5.98: X3.2@4215,4600.71 4321.73,4600.71 C78.2@4325,4597.44 4325,4551.06 R147.2@4323.87,4549.93 4342.38,4531.42 U10.23@4489.8,4531.42
OSC25_OUT: C79.2 R147.1 U10.24 X3.1 | length 337.1
  Top Layer w5.98: X3.1@4215,4439.29 4324.93,4439.29 C79.2@4325.2,4439.01 4325.2,4489.28 R147.1@4323.87,4490.61 4344.99,4511.73 U10.24@4489.8,4511.73
RST: H1.2 R7.1 | length 87.4
  Top Layer w6: R7.1@5505.62,4972.67 5568.44,4972.67 H1.2@5585.85,4955.26
RST(ADS8688): FPC1.10 U10.100 | length 1525.5
  Top Layer w6: FPC1.10@4795.49,3913.29 4795.49,3973.7 v1(4796.79,3975) ; U10.100@5340.2,4807.01 5397.99,4807.01 v1(5410,4795)
  Bottom Layer w6: v1(4796.79,3975) 5270,3975 5455,4160 5455,4750 v1(5410,4795)
SDIO_CLK: R33.1 U5.5 U10.113 | length 1379.3
  Top Layer w6: R33.1@4402.2,5851.57 4402.2,5878.42 v1(4402.75,5878.98) U5.5@4402.75,6018.98 ; v1(5145,5160) 5180.75,5124.25 U10.113@5180.75,5045.2
  Bottom Layer w6: v1(4402.75,5878.98) 4402.75,5807.25 5050,5160 v1(5145,5160)
SDIO_CMD: R30.1 U5.3 U10.116 | length 1262.9
  Top Layer w6: R30.1@4488.59,5852.04 4488.59,5878.2 v1(4489.37,5878.98) U5.3@4489.37,6018.98 ; v1(5120,5180.99) 5121.69,5179.3 U10.116@5121.69,5045.2
  Bottom Layer w6: v1(4489.37,5878.98) 4489.37,5811.62 v1(5120,5180.99)
SDIO_D0: R29.1 U5.7 U10.98 | length 1759.1
  Top Layer w6: U5.7@4316.14,6018.98 v1(4316.14,5878.98) 4316.8,5878.31 R29.1@4316.8,5851.85 ; v1(5284.02,4763.55) 5288.11,4767.64 U10.98@5340.2,4767.64
  Bottom Layer w6: v1(4316.14,5878.98) 5225.11,4970 5255,4970 5284.02,4940.98 v1(5284.02,4763.55)
SDIO_D1: R28.1 U5.8 U10.99 | length 1763.9
  Top Layer w6: R28.1@4272.62,5853.12 4272.62,6018.77 U5.8@4272.83,6018.98 ; v1(5259.92,4796.14) 5268.75,4787.32 U10.99@5340.2,4787.32
  Bottom Layer w6: v1(4272.47,5878.11) 5200.58,4950 5240,4950 5259.92,4930.08 v1(5259.92,4796.14)
SDIO_D2: R32.1 U5.1 U10.111 | length 1268
  Top Layer w6: R32.1@4574.52,5852.06 4574.63,5852.16 v1(4574.63,5878.28) 4574.63,6017.62 U5.1@4575.98,6018.98 ; v1(5166.21,5221.21) 5220.12,5167.31 U10.111@5220.12,5045.2
  Bottom Layer w6: v1(4574.63,5878.28) 4574.63,5812.8 v1(5166.21,5221.21)
SDIO_D3: R31.1 U5.2 U10.112 | length 1277.1
  Top Layer w6: R31.1@4532.15,5852.15 v1(4532.15,5878.45) 4532.68,5878.98 U5.2@4532.68,6018.98 ; v1(5145,5200) 5200.43,5144.57 U10.112@5200.43,5045.2
  Bottom Layer w6: v1(4532.15,5878.45) 4532.15,5812.85 v1(5145,5200)
SPI1_CS: FPC1.14 U10.40 | length 317.6
  Top Layer w6: U10.40@4629.57,4194.8 4629.57,4135.43 4716.75,4048.25 FPC1.14@4716.75,3913.29
SPI1_MISO: FPC1.12 U10.42 | length 317.6
  Top Layer w6: U10.42@4668.94,4194.8 4668.94,4136.06 4756.12,4048.88 FPC1.12@4756.12,3913.29
SPI1_MOSI: FPC1.11 U10.43 | length 317.6
  Top Layer w6: U10.43@4688.62,4194.8 4688.62,4131.38 4775.8,4044.2 FPC1.11@4775.8,3913.29
SPI1_SCK: FPC1.13 U10.41 | length 317.6
  Top Layer w6: U10.41@4649.25,4194.8 4649.25,4135.75 4736.43,4048.57 FPC1.13@4736.43,3913.29
SYS_JTCK-SWCLK: D10.1 R8.2 U10.109 | length 310.3
  Top Layer w6: U10.109@5259.49,5045.2 5259.49,5084.49 5312.78,5137.78 D10.1@5448.3,5137.78 5455.53,5130.56 R8.2@5505.48,5130.56
SYS_JTCK-SWDIO: D11.1 R9.2 U10.105 | length 310.8
  Top Layer w6: U10.105@5340.2,4905.43 5400.43,4905.43 5420,4925 5420,5048.6 D11.1@5448.63,5077.24 5453.02,5081.62 R9.2@5505.63,5081.62
UB: U2.40 U10.141 | length 328.2
  Top Layer w6: U10.141@4629.57,5045.2 4629.57,4988.24 v1(4635.14,4982.67)
  Bottom Layer w6: v1(4635.14,4982.67) 4636.4,4981.41 4636.4,4967.51 4632.16,4963.26 4624.64,4963.26 4620.4,4959.02 4620.4,4947.82 4624.64,4943.58 4648.17,4943.58 4652.41,4939.34 4652.41,4928.14 4648.17,4923.89 4640.65,4923.89 4636.4,4919.65 4636.4,4833.6 4645.28,4824.72 U2.40@4697.34,4824.72
USART1_RX: H7.3 U10.102 | length 582.1
  Top Layer w6: U10.102@5340.2,4846.38 5388.62,4846.38 5394.92,4840.08 5469.92,4840.08 5515,4795 5515,4540.91 5555,4500.91 5584.61,4500.91 5588.85,4505.15 H7.3@5588.85,4544.91
USART1_TX: H7.4 U10.101 | length 578.9
  Top Layer w6: U10.101@5340.2,4826.69 5466.34,4826.69 5503,4790.03 5503,4535.94 5550.03,4488.91 5584.61,4488.91 5588.85,4484.67 H7.4@5588.85,4444.91
USART2_RX: H8.3 U10.37 | length 740
  Top Layer w6: H8.3@3937.62,4081.93 3981.62,4125.93 3992.59,4125.93 4044.65,4178 4494.97,4178 4556.97,4240 4564.49,4240 4570.51,4233.98 U10.37@4570.51,4194.8
USART2_TX: H8.4 U10.36 | length 739.5
  Top Layer w6: H8.4@3937.62,4181.93 3981.62,4137.93 3987.62,4137.93 4039.68,4190 4485,4190 4540,4245 4540,4265 4529.49,4275.51 U10.36@4489.8,4275.51
USB_OTG_FS_DM: R22.1 U10.103 | length 1568.5
  Top Layer w6: R22.1@5236.98,6029.96 5213.33,6053.6 5207.18,6053.6 5197,6043.42 5197,5869.97 5243.49,5823.49 5326.21,5823.49 v1(5328.95,5820.75) ; U10.103@5340.2,4866.06 5410.74,4866.06 v1(5415.72,4861.08)
  Bottom Layer w6: v1(5328.95,5820.75) 5336.68,5813.02 5336.68,5730.29 5509.01,5557.96 5509.01,4889.01 5490.13,4870.13 5442.78,4870.13 5433.73,4861.08 v1(5415.72,4861.08)
USB_OTG_FS_DP: R21.1 U10.104 | length 1568.4
  Top Layer w6: R21.1@5236.83,6089.25 5213.18,6065.6 5202.21,6065.6 5185,6048.39 5185,5865 5245,5805 5302.27,5805 v1(5311.97,5795.31) ; U10.104@5340.2,4885.75 5410.42,4885.75 v1(5415.84,4891.18)
  Bottom Layer w6: v1(5311.97,5795.31) 5315.47,5791.81 5315.47,5734.53 5324.14,5725.86 5324.14,5719.86 5321.41,5717.12 5321.41,5711.12 5323.89,5708.64 5329.89,5708.64 5332.63,5711.37 5338.63,5711.37 5497.01,5552.99 5497.01,4893.98 5485.16,4882.13 5442.9,4882.13 5433.85,4891.18 v1(5415.84,4891.18)
WE: U2.17 U10.119 | length 671.5
  Top Layer w6: v1(5060,4740) 5062.64,4742.64 U10.119@5062.64,5045.2
  Bottom Layer w6: v1(5060,4740) 5060,4491.62 5065.25,4486.37 5065.25,4459.75 5078.23,4446.77 U2.17@5142.66,4446.77
WKUP: R2.1 U10.34 | length 515.1
  Top Layer w6: R2.1@4092.87,4455.47 4093.02,4455.32 v1(4093.02,4433.76) ; v1(4425,4305) 4434.88,4314.88 U10.34@4489.8,4314.88
  Bottom Layer w6: v1(4093.02,4433.76) 4093.02,4366.98 4155,4305 v1(4425,4305)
